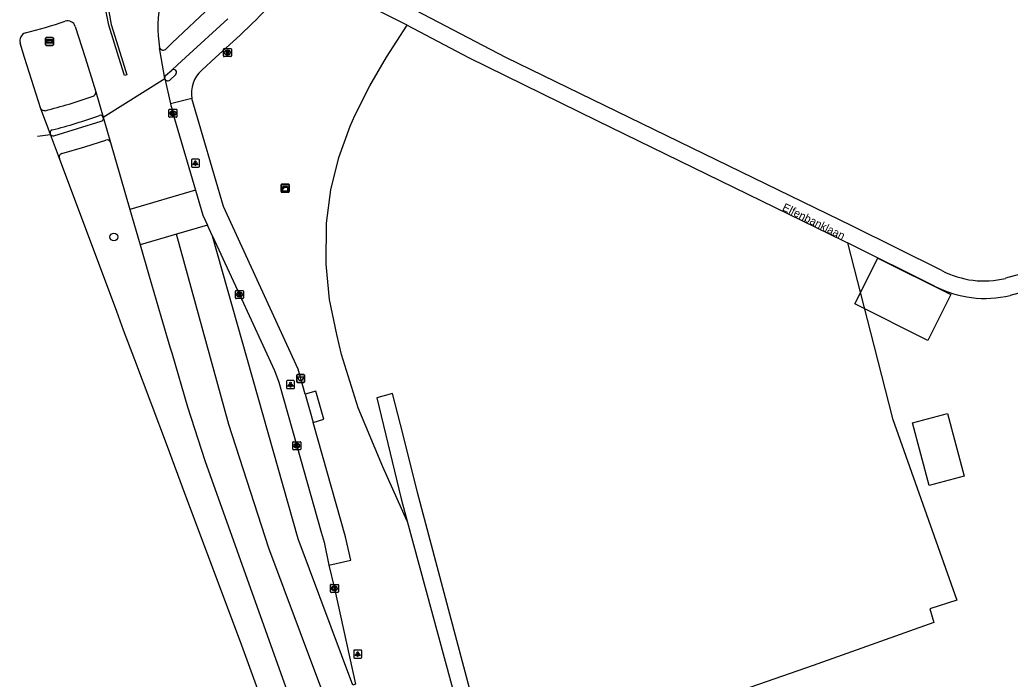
# Model space of a CAD drawing. Extents: x 162675 to 163482, y 379761 to 381227.
# Drawn here: x 162684.2 to 162807.8, y 380672.3 to 380754.7 of the extents above; entities that cross this region are included whole.
import ezdxf

# ---------------------------------------------------------------- set-up
doc = ezdxf.new("R2010")
doc.units = 0
for name, color, linetype in [('IMGEO_Afvalbak', 7, 'Continuous'), ('IMGEO_Berm_groen', 7, 'Continuous'), ('IMGEO_Boom', 7, 'Continuous'), ('IMGEO_Fietspad_gesloten', 7, 'Continuous'), ('IMGEO_Fietspad_open', 7, 'Continuous'), ('IMGEO_Groenvoorziening', 7, 'Continuous'), ('IMGEO_Hek', 7, 'Continuous'), ('IMGEO_Kast', 7, 'Continuous'), ('IMGEO_Kolk', 7, 'Continuous'), ('IMGEO_Lichtpunt', 7, 'Continuous'), ('IMGEO_Openbare_ruimte_label', 7, 'Continuous'), ('IMGEO_Pand', 7, 'Continuous'), ('IMGEO_Pand_vergunning_verleend', 7, 'Continuous'), ('IMGEO_Rijbaan_lokaal_gesloten', 7, 'Continuous'), ('IMGEO_Rijbaan_regionaal_gesloten', 7, 'Continuous'), ('IMGEO_Rioolput', 7, 'Continuous'), ('IMGEO_Voetpad_gesloten', 7, 'Continuous'), ('IMGEO_Voetpad_open', 7, 'Continuous'), ('IMGEO_Waterloop', 7, 'Continuous'), ('IMGEO_Wegwijzer', 7, 'Continuous')]:
    doc.layers.add(name, color=color, linetype=linetype)

msp = doc.modelspace()

# ---------------------------------------------------------------- linework, layer by layer
at = {"layer": 'IMGEO_Afvalbak'}
for p, q in [((162718.74, 380709.47), (162718.74, 380710.27)), ((162718.74, 380710.27), (162718.74, 380709.47)), ((162718.84, 380710.37), (162719.63, 380710.37)), ((162719.63, 380710.37), (162718.84, 380710.37)), ((162719.73, 380710.27), (162719.73, 380709.47)), ((162719.73, 380709.47), (162719.73, 380710.27)), ((162719.63, 380709.37), (162718.84, 380709.37)), ((162718.84, 380709.37), (162719.63, 380709.37))]:
    msp.add_line(p, q, dxfattribs=at)
msp.add_lwpolyline([(162718.89, 380710.08), (162719.59, 380710.08), (162719.44, 380709.61), (162719.04, 380709.61), (162718.89, 380710.08)], dxfattribs=at)
for centre, start, end in [((162718.84, 380710.27), 90, 180), ((162718.84, 380710.27), 90, 180), ((162719.63, 380710.27), 0, 90), ((162719.63, 380710.27), 360, 90), ((162718.84, 380709.47), 180, 270), ((162718.84, 380709.47), 180, 270), ((162719.63, 380709.47), 270, 0), ((162719.63, 380709.47), 270, 0)]:
    msp.add_arc(centre, 0.1, start, end, dxfattribs=at)
at = {"layer": 'IMGEO_Berm_groen'}
msp.add_lwpolyline([(162732.55, 380692.05), (162729.49, 380698.81), (162726.4, 380706.21), (162724.34, 380712.88), (162723.77, 380715.36), (162722.85, 380719.73), (162722.4, 380724.18), (162722.45, 380729.29), (162723.01, 380733.43), (162724.01, 380737.48), (162725.42, 380741.42), (162726, 380742.74), (162727.88, 380746.45), (162729.94, 380750.05), (162732.52, 380754.04)], dxfattribs=at)
at = {"layer": 'IMGEO_Boom'}
msp.add_circle((162695.91, 380727.56), 0.489, dxfattribs=at)
at = {"layer": 'IMGEO_Fietspad_gesloten'}
for points in [[(162708.69, 380756.97), (162704.61, 380753.16), (162703.14, 380751.8), (162702.43, 380751.06)], [(162703.13, 380748.4), (162703.86, 380749.08), (162704.87, 380750), (162710.16, 380754.83)], [(162702.27, 380747.35), (162702.37, 380747.72), (162703.13, 380748.4)]]:
    msp.add_lwpolyline(points, dxfattribs=at)
msp.add_arc((162702.08, 380751.43), 0.51, 207.4038, 314.3604, dxfattribs=at)
at = {"layer": 'IMGEO_Fietspad_open'}
for centre, radius, start, end in [((162669.84, 380812.46), 71.29, 284.184, 289.2197), ((162693.12, 380745.67), 0.552, 289.4754, 0.7739), ((162687.23, 380743.86), 0.516, 213.4808, 278.1301), ((162672.68, 380802.14), 63.14, 284.2243, 289.8618), ((162694.22, 380742.39), 0.38, 22.1966, 104.263), ((162688.33, 380740.57), 0.389, 110.9564, 189.8988)]:
    msp.add_arc(centre, radius, start, end, dxfattribs=at)
at = {"layer": 'IMGEO_Groenvoorziening'}
msp.add_lwpolyline([(162787.52, 380726.82), (162790.41, 380715.6), (162793.16, 380704.88), (162801.19, 380682.16), (162797.79, 380681.08), (162798.32, 380679.38), (162783.25, 380674.01), (162743.23, 380660.08)], dxfattribs=at)
at = {"layer": 'IMGEO_Hek'}
for points in [[(162787.52, 380726.82), (162790.41, 380715.6)], [(162790.41, 380715.6), (162793.16, 380704.88), (162801.19, 380682.16), (162797.79, 380681.08), (162798.32, 380679.38), (162783.25, 380674.01)]]:
    msp.add_lwpolyline(points, dxfattribs=at)
at = {"layer": 'IMGEO_Kast'}
for p, q in [((162716.8, 380733.23), (162716.8, 380734.07)), ((162716.8, 380734.07), (162716.8, 380733.23)), ((162716.87, 380734.16), (162717.71, 380734.16)), ((162717.71, 380734.16), (162716.87, 380734.16)), ((162717.8, 380734.08), (162717.8, 380733.24)), ((162717.8, 380733.24), (162717.8, 380734.08)), ((162717.72, 380733.16), (162716.88, 380733.16)), ((162716.88, 380733.16), (162717.72, 380733.16))]:
    msp.add_line(p, q, dxfattribs=at)
for points in [[(162716.99, 380733.95), (162717.59, 380733.95), (162717.59, 380733.86), (162716.99, 380733.86), (162716.99, 380733.95)], [(162716.99, 380733.77), (162717.59, 380733.77), (162717.59, 380733.28), (162716.99, 380733.28), (162716.99, 380733.77)]]:
    msp.add_lwpolyline(points, dxfattribs=at)
msp.add_circle((162717.07, 380733.62), 0.0377, dxfattribs=at)
for centre, start, end in [((162716.87, 380734.08), 92.4484, 184.2845), ((162716.87, 380734.08), 92.4484, 184.2845), ((162717.72, 380734.08), 2.4484, 94.2845), ((162717.72, 380734.08), 2.4484, 94.2845), ((162716.87, 380733.23), 182.4484, 274.2845), ((162716.87, 380733.23), 182.4484, 274.2845), ((162717.72, 380733.23), 272.4484, 4.2845), ((162717.72, 380733.23), 272.4484, 4.2845)]:
    msp.add_arc(centre, 0.0779, start, end, dxfattribs=at)
at = {"layer": 'IMGEO_Kolk'}
for p, q in [((162702.78, 380742.59), (162702.78, 380743.45)), ((162702.86, 380743.52), (162703.71, 380743.52)), ((162703.27, 380743.3), (162703.3, 380743.3)), ((162703.78, 380743.45), (162703.78, 380742.59)), ((162703.71, 380742.52), (162702.86, 380742.52)), ((162703.29, 380742.74), (162703.27, 380742.74)), ((162711.1, 380719.94), (162711.1, 380720.79)), ((162711.17, 380720.87), (162712.02, 380720.87)), ((162712.02, 380719.87), (162711.17, 380719.87)), ((162711.61, 380720.09), (162711.58, 380720.09)), ((162711.59, 380720.65), (162711.61, 380720.65)), ((162712.1, 380720.79), (162712.1, 380719.94)), ((162718.25, 380701.04), (162718.25, 380701.9)), ((162718.32, 380701.97), (162719.18, 380701.97)), ((162718.74, 380701.75), (162718.76, 380701.75)), ((162719.25, 380701.9), (162719.25, 380701.04)), ((162719.18, 380700.97), (162718.32, 380700.97)), ((162718.76, 380701.19), (162718.74, 380701.19)), ((162722.95, 380683.22), (162722.95, 380684.07)), ((162723.03, 380684.14), (162723.88, 380684.14)), ((162723.44, 380683.92), (162723.46, 380683.92)), ((162723.95, 380684.07), (162723.95, 380683.22)), ((162723.88, 380683.14), (162723.03, 380683.14)), ((162723.46, 380683.36), (162723.44, 380683.36))]:
    msp.add_line(p, q, dxfattribs=at)
for points in [[(162702.78, 380742.59), (162702.78, 380743.45)], [(162702.86, 380743.52), (162703.71, 380743.52)], [(162703.78, 380743.45), (162703.78, 380742.59)], [(162703.71, 380742.52), (162702.86, 380742.52)], [(162703.1, 380743.22), (162703.23, 380743.22), (162703.23, 380743.07), (162703.36, 380743.22), (162703.52, 380743.22), (162703.37, 380743.07), (162703.53, 380742.82), (162703.37, 380742.82), (162703.29, 380742.98), (162703.23, 380742.92), (162703.23, 380742.82), (162703.1, 380742.82), (162703.1, 380743.22)], [(162711.1, 380719.94), (162711.1, 380720.79)], [(162711.17, 380720.87), (162712.02, 380720.87)], [(162712.02, 380719.87), (162711.17, 380719.87)], [(162711.42, 380720.57), (162711.54, 380720.57), (162711.54, 380720.41), (162711.67, 380720.57), (162711.84, 380720.57), (162711.69, 380720.42), (162711.84, 380720.17), (162711.69, 380720.17), (162711.61, 380720.33), (162711.54, 380720.26), (162711.54, 380720.17), (162711.42, 380720.17), (162711.42, 380720.57)], [(162712.1, 380720.79), (162712.1, 380719.94)], [(162718.25, 380701.04), (162718.25, 380701.9)], [(162718.32, 380701.97), (162719.18, 380701.97)], [(162718.57, 380701.67), (162718.69, 380701.67), (162718.69, 380701.52), (162718.82, 380701.67), (162718.99, 380701.67), (162718.84, 380701.52), (162718.99, 380701.27), (162718.84, 380701.27), (162718.76, 380701.43), (162718.69, 380701.37), (162718.69, 380701.27), (162718.57, 380701.27), (162718.57, 380701.67)], [(162719.25, 380701.9), (162719.25, 380701.04)], [(162719.18, 380700.97), (162718.32, 380700.97)], [(162722.95, 380683.22), (162722.95, 380684.07)], [(162723.03, 380684.14), (162723.88, 380684.14)], [(162723.95, 380684.07), (162723.95, 380683.22)], [(162723.88, 380683.14), (162723.03, 380683.14)], [(162723.27, 380683.84), (162723.4, 380683.84), (162723.4, 380683.69), (162723.52, 380683.84), (162723.69, 380683.84), (162723.54, 380683.69), (162723.7, 380683.44), (162723.54, 380683.44), (162723.46, 380683.61), (162723.4, 380683.54), (162723.4, 380683.44), (162723.27, 380683.44), (162723.27, 380683.84)]]:
    msp.add_lwpolyline(points, dxfattribs=at)
for centre, start, end in [((162702.86, 380743.44), 91.552, 178.448), ((162702.86, 380743.44), 91.552, 178.448), ((162703.71, 380743.44), 1.552, 88.448), ((162703.71, 380743.44), 1.552, 88.448), ((162702.86, 380742.6), 181.552, 268.448), ((162702.86, 380742.6), 181.552, 268.448), ((162703.71, 380742.6), 271.552, 358.448), ((162703.71, 380742.6), 271.552, 358.448), ((162711.17, 380720.79), 91.552, 178.448), ((162711.17, 380720.79), 91.552, 178.448), ((162711.17, 380719.94), 181.552, 268.448), ((162711.17, 380719.94), 181.552, 268.448), ((162712.02, 380720.79), 1.552, 88.448), ((162712.02, 380720.79), 1.552, 88.448), ((162712.02, 380719.94), 271.552, 358.448), ((162712.02, 380719.94), 271.552, 358.448), ((162718.33, 380701.89), 91.552, 178.448), ((162718.33, 380701.89), 91.552, 178.448), ((162719.17, 380701.89), 1.552, 88.448), ((162719.17, 380701.89), 1.552, 88.448), ((162718.33, 380701.04), 181.552, 268.448), ((162718.33, 380701.04), 181.552, 268.448), ((162719.17, 380701.04), 271.552, 358.448), ((162719.17, 380701.04), 271.552, 358.448), ((162723.03, 380684.07), 91.552, 178.448), ((162723.03, 380684.07), 91.552, 178.448), ((162723.88, 380684.07), 1.552, 88.448), ((162723.88, 380684.07), 1.552, 88.448), ((162723.03, 380683.22), 181.552, 268.448), ((162723.03, 380683.22), 181.552, 268.448), ((162723.88, 380683.22), 271.552, 358.448), ((162723.88, 380683.22), 271.552, 358.448)]:
    msp.add_arc(centre, 0.0765, start, end, dxfattribs=at)
for centre, major_axis, ratio, start_param, end_param in [((162703.27, 380743.02), (-0.387, 0.002), 0.722429, 4.712389, 7.853982), ((162703.29, 380743.02), (-0.39, 0.002), 0.717154, 1.570796, 4.712389), ((162711.58, 380720.37), (-0.387, 0.002), 0.722429, 4.712389, 7.853982), ((162711.61, 380720.37), (-0.39, 0.002), 0.717154, 1.570796, 4.712389), ((162718.74, 380701.47), (-0.387, 0.002), 0.722429, 4.712389, 7.853982), ((162718.76, 380701.47), (-0.39, 0.002), 0.717154, 1.570796, 4.712389), ((162723.44, 380683.64), (-0.387, 0.002), 0.722429, 4.712389, 7.853982), ((162723.46, 380683.64), (-0.39, 0.002), 0.717154, 1.570796, 4.712389)]:
    msp.add_ellipse(centre, major_axis=major_axis, ratio=ratio, start_param=start_param, end_param=end_param, dxfattribs=at)
at = {"layer": 'IMGEO_Lichtpunt'}
for p, q in [((162705.59, 380737.19), (162705.59, 380736.38)), ((162705.59, 380737.19), (162705.59, 380736.38)), ((162706.49, 380737.29), (162705.69, 380737.29)), ((162706.49, 380737.29), (162705.69, 380737.29)), ((162706.59, 380736.38), (162706.59, 380737.19)), ((162706.59, 380736.38), (162706.59, 380737.19)), ((162705.69, 380736.29), (162706.49, 380736.29)), ((162705.69, 380736.29), (162706.49, 380736.29)), ((162717.47, 380709.5), (162717.47, 380708.7)), ((162717.47, 380709.5), (162717.47, 380708.7)), ((162718.37, 380709.6), (162717.56, 380709.6)), ((162718.37, 380709.6), (162717.56, 380709.6)), ((162718.47, 380708.7), (162718.47, 380709.5)), ((162718.47, 380708.7), (162718.47, 380709.5)), ((162717.56, 380708.6), (162718.37, 380708.6)), ((162717.56, 380708.6), (162718.37, 380708.6)), ((162725.86, 380675.84), (162725.86, 380675.03)), ((162725.86, 380675.84), (162725.86, 380675.03)), ((162726.76, 380675.93), (162725.95, 380675.93)), ((162726.76, 380675.93), (162725.95, 380675.93)), ((162726.86, 380675.03), (162726.86, 380675.84)), ((162726.86, 380675.03), (162726.86, 380675.84)), ((162725.95, 380674.93), (162726.76, 380674.93)), ((162725.95, 380674.93), (162726.76, 380674.93))]:
    msp.add_line(p, q, dxfattribs=at)
for points in [[(162705.97, 380736.85), (162706, 380736.83), (162705.82, 380736.56), (162705.78, 380736.59), (162705.97, 380736.85)], [(162706.07, 380736.81), (162706.11, 380736.81), (162706.11, 380736.48), (162706.07, 380736.48), (162706.07, 380736.81)], [(162706.18, 380736.83), (162706.22, 380736.85), (162706.4, 380736.59), (162706.36, 380736.56), (162706.18, 380736.83)], [(162717.84, 380709.17), (162717.88, 380709.14), (162717.69, 380708.88), (162717.66, 380708.91), (162717.84, 380709.17)], [(162717.94, 380709.12), (162717.99, 380709.12), (162717.99, 380708.8), (162717.94, 380708.8), (162717.94, 380709.12)], [(162718.05, 380709.14), (162718.09, 380709.17), (162718.28, 380708.9), (162718.24, 380708.88), (162718.05, 380709.14)], [(162726.23, 380675.5), (162726.27, 380675.47), (162726.08, 380675.21), (162726.05, 380675.24), (162726.23, 380675.5)], [(162726.33, 380675.45), (162726.38, 380675.45), (162726.38, 380675.13), (162726.33, 380675.13), (162726.33, 380675.45)], [(162726.44, 380675.47), (162726.48, 380675.5), (162726.67, 380675.24), (162726.63, 380675.21), (162726.44, 380675.47)]]:
    msp.add_lwpolyline(points, dxfattribs=at)
for centre in [(162706.09, 380736.99), (162717.97, 380709.3), (162726.36, 380675.63)]:
    msp.add_circle(centre, 0.0994, dxfattribs=at)
for centre, start, end in [((162705.69, 380737.19), 90, 180), ((162705.69, 380737.19), 90, 180), ((162706.49, 380737.19), 0, 90), ((162706.49, 380737.19), 0, 90), ((162705.69, 380736.38), 180, 270), ((162705.69, 380736.38), 180, 270), ((162706.49, 380736.38), 270, 0), ((162706.49, 380736.38), 270, 360), ((162717.56, 380709.5), 90, 180), ((162717.56, 380709.5), 90, 180), ((162717.56, 380708.7), 180, 270), ((162717.56, 380708.7), 180, 270), ((162718.37, 380709.5), 0, 90), ((162718.37, 380709.5), 0, 90), ((162718.37, 380708.7), 270, 0), ((162718.37, 380708.7), 270, 360), ((162725.95, 380675.84), 90, 180), ((162725.95, 380675.84), 90, 180), ((162726.76, 380675.84), 0, 90), ((162726.76, 380675.84), 0, 90), ((162725.95, 380675.03), 180, 270), ((162725.95, 380675.03), 180, 270), ((162726.76, 380675.03), 270, 0), ((162726.76, 380675.03), 270, 360)]:
    msp.add_arc(centre, 0.0946, start, end, dxfattribs=at)
at = {"layer": 'IMGEO_Pand'}
msp.add_lwpolyline([(162797.73, 380696.5), (162795.66, 380704.33), (162800.02, 380705.48), (162802.08, 380697.65), (162797.73, 380696.5)], dxfattribs=at)
at = {"layer": 'IMGEO_Pand_vergunning_verleend'}
msp.add_lwpolyline([(162788.46, 380719.21), (162791.33, 380724.92), (162800.42, 380720.35), (162797.54, 380714.64), (162788.46, 380719.21)], dxfattribs=at)
at = {"layer": 'IMGEO_Rijbaan_lokaal_gesloten'}
for points in [[(162702.27, 380747.35), (162702.96, 380744.21)], [(162702.96, 380744.21), (162703.03, 380743.97), (162703.13, 380743.64), (162703.28, 380743.02), (162706.1, 380733.41)], [(162694.57, 380742.53), (162695.49, 380739.38)], [(162695.49, 380739.38), (162697.92, 380731)], [(162706.1, 380733.41), (162697.92, 380731)], [(162706.1, 380733.41), (162707.01, 380730.3), (162707.6, 380729.05)], [(162697.92, 380731), (162699.2, 380726.57)], [(162708.24, 380727.68), (162711.6, 380720.37), (162715.95, 380710.86), (162716.5, 380709.4), (162718.75, 380701.47), (162721.79, 380690.65), (162722.15, 380689.41), (162722.77, 380686.55)], [(162722.77, 380686.55), (162723.45, 380683.64), (162726.07, 380671.66)]]:
    msp.add_lwpolyline(points, dxfattribs=at)
at = {"layer": 'IMGEO_Rijbaan_regionaal_gesloten'}
for points in [[(162697.52, 380747.81), (162697.23, 380747.72), (162696.53, 380750), (162695.29, 380754.04), (162694.96, 380755.68), (162694.83, 380756.68), (162695.14, 380756.72), (162695.26, 380755.72), (162695.58, 380754.12), (162696.85, 380750), (162697.52, 380747.81)], [(162691.08, 380753.88), (162692.31, 380750), (162693.67, 380745.68)], [(162686.8, 380743.58), (162684.76, 380750), (162684.2, 380751.78)], [(162702.27, 380747.35), (162701.82, 380750), (162701.62, 380751.19)], [(162694.57, 380742.53), (162702.27, 380747.35)], [(162693.67, 380745.68), (162694.57, 380742.53)], [(162687.95, 380740.5), (162686.8, 380743.58)], [(162686.38, 380740.14), (162687.99, 380740.38)], [(162687.99, 380740.38), (162687.95, 380740.5)], [(162689.11, 380737.38), (162687.99, 380740.38)], [(162722.59, 380645.49), (162715.54, 380666.42), (162711.71, 380676.95), (162704.79, 380695.48), (162702.59, 380701.36), (162698.52, 380712.2), (162697.12, 380715.92), (162696.26, 380718.23), (162689.11, 380737.38)], [(162707.6, 380729.05), (162703.71, 380727.9)], [(162708.24, 380727.68), (162707.6, 380729.05)], [(162703.71, 380727.9), (162699.2, 380726.57)], [(162843.14, 380247.81), (162835.6, 380276.1), (162826.23, 380311.17), (162807.86, 380379.44), (162801.46, 380402.48), (162795.45, 380425.78), (162788.92, 380449.59), (162779.6, 380483.79), (162773.68, 380505.98), (162767.16, 380529.98), (162758.34, 380561.08), (162753.96, 380575.32), (162746.99, 380598.08), (162743.65, 380609.98), (162735.76, 380632.97), (162727.66, 380655.65), (162721.15, 380672.97), (162715.24, 380688.66), (162710.25, 380704.14), (162703.71, 380727.9)], [(162726.07, 380671.66), (162725.75, 380671.55), (162718.92, 380689.84), (162708.24, 380727.68)], [(162699.2, 380726.57), (162700.33, 380722.66), (162701.79, 380717.66), (162702.9, 380713.83), (162703.13, 380713.06), (162705.1, 380706.32), (162707.26, 380699.61), (162719.05, 380666.59), (162718.87, 380666.52), (162722.14, 380657.75), (162726.18, 380646.81)]]:
    msp.add_lwpolyline(points, dxfattribs=at)
for centre, radius, start, end in [((162715.75, 380753.73), 14.35, 166.0775, 190.1737), ((162669.43, 380814.98), 63.81, 283.9955, 288.6461), ((162690.14, 380753.58), 0.991, 17.5194, 108.3702), ((162685.24, 380752.06), 1.08, 110.7992, 194.9033)]:
    msp.add_arc(centre, radius, start, end, dxfattribs=at)
at = {"layer": 'IMGEO_Rioolput'}
for p, q in [((162709.59, 380750.18), (162709.59, 380751.03)), ((162709.67, 380751.11), (162710.52, 380751.11)), ((162710.08, 380750.89), (162710.1, 380750.89)), ((162710.59, 380751.03), (162710.59, 380750.18)), ((162710.52, 380750.11), (162709.67, 380750.11)), ((162710.1, 380750.33), (162710.08, 380750.33))]:
    msp.add_line(p, q, dxfattribs=at)
for points in [[(162709.59, 380750.18), (162709.59, 380751.03)], [(162709.67, 380751.11), (162710.52, 380751.11)], [(162710.18, 380750.8), (162709.93, 380750.81), (162709.93, 380750.41)], [(162710.11, 380750.73), (162710.05, 380750.73), (162710.05, 380750.64)], [(162710.59, 380751.03), (162710.59, 380750.18)], [(162710.52, 380750.11), (162709.67, 380750.11)], [(162709.93, 380750.41), (162710.05, 380750.41), (162710.05, 380750.57), (162710.06, 380750.57)], [(162710.05, 380750.64), (162710.1, 380750.64)], [(162710.11, 380750.54), (162710.18, 380750.41), (162710.32, 380750.41), (162710.26, 380750.53)]]:
    msp.add_lwpolyline(points, dxfattribs=at)
for centre, radius, start, end in [((162709.67, 380751.03), 0.0765, 91.552, 178.448), ((162709.67, 380751.03), 0.0765, 91.552, 178.448), ((162710.11, 380750.63), 0.0964, 77.0061, 93.1865), ((162710.13, 380750.69), 0.0378, 276.6634, 79.6772), ((162710.18, 380750.69), 0.109, 350.3612, 89.416), ((162710.18, 380750.69), 0.112, 277.5842, 350.9817), ((162710.52, 380751.03), 0.0765, 1.552, 88.448), ((162710.52, 380751.03), 0.0765, 1.552, 88.448), ((162709.67, 380750.18), 0.0765, 181.552, 268.448), ((162709.67, 380750.18), 0.0765, 181.552, 268.448), ((162710.06, 380750.52), 0.0533, 26.0293, 88.6989), ((162710.09, 380750.83), 0.19, 274.7715, 282.9687), ((162710.16, 380750.48), 0.108, 29.5134, 73.7905), ((162710.52, 380750.18), 0.0765, 271.552, 358.448), ((162710.52, 380750.18), 0.0765, 271.552, 358.448)]:
    msp.add_arc(centre, radius, start, end, dxfattribs=at)
for centre, major_axis, ratio, start_param, end_param in [((162710.08, 380750.61), (-0.387, 0.002), 0.722429, 4.712389, 7.853982), ((162710.1, 380750.61), (-0.39, 0.002), 0.717154, 1.570796, 4.712389)]:
    msp.add_ellipse(centre, major_axis=major_axis, ratio=ratio, start_param=start_param, end_param=end_param, dxfattribs=at)
at = {"layer": 'IMGEO_Voetpad_gesloten'}
for points in [[(162720.79, 380704.38), (162722.11, 380704.77), (162721.12, 380708.29), (162719.79, 380707.93)], [(162719.79, 380707.93), (162720.79, 380704.38)]]:
    msp.add_lwpolyline(points, dxfattribs=at)
at = {"layer": 'IMGEO_Voetpad_open'}
for points in [[(162732.52, 380754.04), (162725.18, 380757.75), (162719.14, 380760.93)], [(162799.32, 380723.36), (162788.16, 380728.91), (162744.86, 380750), (162733.6, 380755.87)], [(162732.52, 380754.04), (162740.21, 380750), (162751.66, 380744.36), (162756.23, 380742.12), (162787.02, 380727.08), (162787.52, 380726.82)], [(162711.66, 380752.8), (162708.62, 380750), (162706.88, 380748.41)], [(162703.64, 380747.86), (162702.88, 380747.16)], [(162705.66, 380744.85), (162702.96, 380744.21)], [(162719.79, 380707.93), (162718.91, 380711.05), (162709.59, 380731.36), (162705.66, 380744.85)], [(162688.39, 380740.22), (162694.34, 380742.03), (162694.45, 380742.07), (162694.54, 380742.14), (162694.61, 380742.33), (162694.57, 380742.53)], [(162689.41, 380737.99), (162692.3, 380738.83), (162694.89, 380739.67)], [(162845.6, 380732.65), (162841.32, 380731.52), (162807.25, 380722.39)], [(162847.76, 380730.99), (162822.96, 380724.29), (162807.84, 380720.25)], [(162798.38, 380721.42), (162787.52, 380726.82)], [(162722.77, 380686.55), (162725.51, 380687.15), (162724.83, 380690.08), (162720.79, 380704.38)]]:
    msp.add_lwpolyline(points, dxfattribs=at)
for centre, radius, start, end in [((162668.94, 380799.53), 63.32, 312.4318, 322.4403), ((162703.36, 380748.11), 0.374, 316.4033, 129.4749), ((162709.46, 380745.53), 3.86, 131.9115, 190.1576), ((162702.63, 380747.46), 0.382, 195.621, 310.1604), ((162688.31, 380740.6), 0.39, 215.1748, 281.0215), ((162695.03, 380739.2), 0.496, 21.4092, 106.2272), ((162689.55, 380737.54), 0.469, 107.4494, 200.0252), ((162804.56, 380733.23), 11.17, 242.0363, 283.9484), ((162804.69, 380733.56), 13.68, 242.5403, 283.3349)]:
    msp.add_arc(centre, radius, start, end, dxfattribs=at)
at = {"layer": 'IMGEO_Waterloop'}
for points in [[(162743.23, 380660.08), (162742.06, 380664.58), (162733.81, 380695.64), (162732.02, 380702.81), (162730.69, 380708), (162728.75, 380707.45), (162731.79, 380694.84), (162732.55, 380692.05)], [(162732.55, 380692.05), (162772.78, 380543.61)]]:
    msp.add_lwpolyline(points, dxfattribs=at)
at = {"layer": 'IMGEO_Wegwijzer'}
for p, q in [((162687.37, 380751.59), (162687.37, 380752.39)), ((162687.37, 380752.39), (162687.37, 380751.59)), ((162687.47, 380752.49), (162688.26, 380752.49)), ((162688.26, 380752.49), (162687.47, 380752.49)), ((162688.36, 380752.39), (162688.36, 380751.59)), ((162688.36, 380751.59), (162688.36, 380752.39)), ((162688.26, 380751.49), (162687.47, 380751.49)), ((162687.47, 380751.49), (162688.26, 380751.49))]:
    msp.add_line(p, q, dxfattribs=at)
for points in [[(162687.47, 380752.22), (162688.25, 380752.22), (162688.25, 380751.76), (162687.47, 380751.76), (162687.47, 380752.22)], [(162687.53, 380752.07), (162687.53, 380751.99), (162687.53, 380751.91), (162687.94, 380751.91), (162687.94, 380751.82), (162688.19, 380751.99), (162687.94, 380752.16), (162687.94, 380752.07), (162687.53, 380752.07)]]:
    msp.add_lwpolyline(points, dxfattribs=at)
for centre, start, end in [((162687.47, 380752.39), 90, 180), ((162687.47, 380752.39), 90, 180), ((162688.26, 380752.39), 0, 90), ((162688.26, 380752.39), 360, 90), ((162687.47, 380751.59), 180, 270), ((162687.47, 380751.59), 180, 270), ((162688.26, 380751.59), 270, 0), ((162688.26, 380751.59), 270, 0)]:
    msp.add_arc(centre, 0.1, start, end, dxfattribs=at)

# ---------------------------------------------------------------- texts
at = {"layer": 'IMGEO_Openbare_ruimte_label'}
msp.add_text('Elfenbanklaan', height=1, rotation=333.6399, dxfattribs=at).set_placement((162779.3, 380730.94))

doc.saveas('drawing.dxf')
